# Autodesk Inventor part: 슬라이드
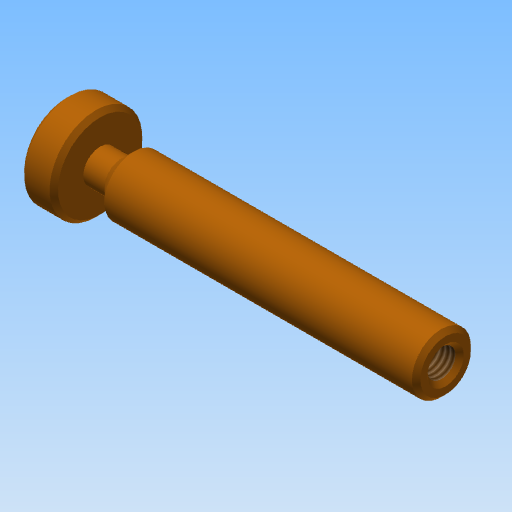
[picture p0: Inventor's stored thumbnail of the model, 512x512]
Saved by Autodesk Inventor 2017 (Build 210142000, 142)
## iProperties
Created: 2015-12
Part Number: 슬라이드
Document SubType Name: Modeling
Designer: mdu
Density: 8.08 g/cm^3
Material: 스테인리스강
Mass: 116.651 g
Surface Area: 50.7862 cm^2
Volume: 14.437 cm^3
Appearance: 주황색
Author: mdu
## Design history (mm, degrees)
sketch "스케치1"
  geometry: L1 (-45, 0)-(45, 0); L2 (-45, 0)-(-45, 11); L3 (-45, 11)-(-37, 11); L4 (-37, 11)-(-37, 4); L5 (-37, 4)-(-32, 4); L6 (-32, 4)-(-29, 7); L7 (-29, 7)-(45, 7); L8 (45, 7)-(45, 0); 2 further points
  constraints: 16 end point, 4 parallel, 2 perpendicular, 1 coincident, 1 horizontal, 1 midpoint
  dimensions: "d0" = 90 distance of L1.start L1.end; "d1" = 22 diameter of L3 L1; "d2" = 14 diameter of L7 L1; "d3" = 8 diameter of L5 L1; "d4" = 8 distance of L2.end L3.end; "d5" = 5 distance of L4.end L5.end; "d6" = 135 deg angle of L6 L5
revolve "회전1" sketch "스케치1" stored, may be unused: angle "d7" = 90 deg
chamfer "모따기1" distance "d8" = 1; stored, may be unused: second distance "d9" = 2, angle "d10" = 45 deg
hole "구멍1" diameter "d13" = 6.647; stored, may be unused: countersink angle "d17" = 90 deg, drill point angle "d19" = 118 deg; dims "d11" = 10, "d12" = 10, "d14" = 9, "d15" = 4, "d16" = 2, "d18" = 12
chamfer "모따기2" distance "d20" = 1; stored, may be unused: second distance "d21" = 2, angle "d22" = 45 deg
node "솔리드1"
